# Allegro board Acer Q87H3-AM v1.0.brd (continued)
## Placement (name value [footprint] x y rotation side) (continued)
PFB8  -  [FB0603_1]  229.71 7.59 0 top
PFB9  -  [FB0805_1]  10.95 212.38 90 top
PFB10  -  [FB0603_1]  50.71 162.97 90 top
PFB11  -  [FB0603_1]  55.66 162.85 270 top
PFB12  -  [FB0805_1]  171.33 214.69 270 top
PFB13  -  [FB0805_1]  169.3 214.69 270 top
PSKM  -  [KB_MS]  234 235.23 270 top
Q1  -  [SOT363_6P]  10.7 237.01 0 top
Q2  -  [SOT363_6P]  18.32 237.01 0 top
Q3  -  [SOT363_6P]  20.86 237.01 0 top
Q4  -  [SOT363_6P]  15.78 237.01 0 top
Q5  -  [SOT363_6P]  6.76 231.05 180 top
Q6  -  [SOT363_6P]  13.24 237.01 0 top
Q7  -  [SOP8_W150_PT50]  103.03 204.63 0 top
QCH1  -  [Q_TDSON8-GDS-4]  161.96 187.74 0 top
QCH2  -  [Q_TDSON8-GDS-4]  179.86 187.74 0 top
QCH3  -  [Q_TDSON8-GDS-4]  213.65 178.34 0 top
QCH4  -  [Q_TDSON8-GDS-4]  142.02 187.74 0 top
QCL1  -  [Q_TDSON8-GDS-4]  156.5 171.1 270 top
QCL2  -  [Q_TDSON8-GDS-4]  177.07 171.1 270 top
QCL3  -  [Q_TDSON8-GDS-4]  222.79 167.29 90 top
QCL4  -  [Q_TDSON8-GDS-4]  137.45 171.1 270 top
QCL5  -  [Q_TDSON8-GDS-4]  156.5 180.5 270 top
QCL6  -  [Q_TDSON8-GDS-4]  177.07 180.5 270 top
QCL7  -  [Q_TDSON8-GDS-4]  222.79 175.42 90 top
QCL8  -  [Q_TDSON8-GDS-4]  137.45 180.5 270 top
QD3H1  -  [Q_TDSON8-GDS-4]  66.33 38.13 180 top
QD3L1  -  [Q_TDSON8-GDS-4]  71.41 53.5 90 top
QD3L2  -  [Q_TDSON8-GDS-4]  71.41 45.12 90 top
QD5H1  -  [Q_TDSON8-GDS-4]  63.28 21.24 0 top
QD5H2  -  [Q_TDSON8-GDS-4]  56.42 21.24 0 top
QD5L1  -  [Q_TDSON8-GDS-4]  49.56 9.18 270 top
QD5L2  -  [Q_TDSON8-GDS-4]  49.56 17.43 270 top
QMH1  -  [Q_TDSON8-GDS-4]  176.31 32.52 0 top
QML1  -  [Q_TDSON8-GDS-4]  170.29 30.26 180 top
QML2  -  [Q_TDSON8-GDS-4]  161.96 30.26 180 top
QN1  -  [SOT23_GDS_2]  203.49 145.83 0 top
QN2  -  [SOT23_BCE_2]  230.79 127.67 0 top
QN3  -  [SOT23_BCE_2]  234.47 127.67 0 top
QN4  -  [SOT23_BCE_2]  234.47 131.6 0 top
QN5  -  [SOT23_BCE_2]  230.79 131.6 0 top
QN6  -  [SOT23_GDS_2]  225.97 221.9 0 top
QN7  -  [SOT23_GDS_2]  218.22 217.33 90 top
QN8  -  [SOT23_GDS_2]  226.85 217.96 0 top
QN9  -  [SOT23_GDS_2]  222.03 217.2 0 top
QN10  -  [SOT23_GDS_2]  222.03 206.28 0 top
QN11  -  [SOT23_GDS_2]  217.08 206.28 0 top
QN12  -  [SOT23_GDS_2]  218.35 212.38 0 top
QN13  -  [SOT23_GDS_2]  222.03 212.38 0 top
QN20  -  [SOT23_GDS_2]  152.56 209.2 0 top
QN21  -  [SOT23_GDS_2]  148.24 209.2 0 top
QN22  -  [SOT23_GDS_2]  182.79 208.57 0 top
QN23  -  [SOT23_GDS_2]  156.5 209.2 0 top
QN24  -  [SOT23_BCE_2]  12.43 157.84 90 top
QN25  -  [SOT23_BCE_2]  12.43 161.53 90 top
QN26  -  [SOT23_BCE_2]  12.43 154.16 270 top
QN27  -  [SOT23_BCE_2]  13.13 165.21 270 top
QN28  -  [SOT23_BCE_2]  230.79 112.81 90 top
QN29  -  [SOT23_BCE_2]  226.98 112.68 0 top
QN30  -  [SOT23_GDS_2]  28.86 149.26 0 top
QN31  -  [SOT23_BCE_2]  28.86 145.32 0 top
QN32  -  [SOT23_BCE_2]  28.86 138.59 0 top
QN33  -  [SOT23_BCE_2]  32.67 138.59 180 top
QN34  -  [SOT23_GDS_2]  32.67 143.29 0 top
QN35  -  [SOT23_BCE_2]  20.73 87.15 90 top
QN36  -  [SOT23_GDS_2]  113.19 34.7 180 top
QN37  -  [SOT23_BCE_2]  123.48 34.7 180 top
QN38  -  [SOT23_GDS_2]  119.79 34.7 180 top
QN39  -  [SOT23_BCE_2]  127.16 34.7 0 top
QN40  -  [SOT23_BCE_2]  231.17 107.22 180 top
QN41  -  [SOT23_BCE_2]  13.24 58.2 90 top
QN42  -  [SOT23_BCE_2]  13.32 53.35 90 top
QN43  -  [SOT23_BCE_2]  10.34 49.66 90 top
QN44  -  [SOT23_GDS_2]  9.25 57.16 270 top
QN45  -  [SOT23_BCE_2]  205.01 203.49 0 top
QN46  -  [SOT23_BCE_2]  4.99 178.34 0 top
QN47  -  [SOT23_GDS_2]  109.89 5.11 90 top
QN48  -  [SOT23_BCE_2]  136.81 26.83 270 top
QN49  -  [SOT23_BCE_2]  129.19 26.07 180 top
QN50  -  [TO252_GDS]  145.96 9.43 0 top
QN51  -  [SOT23_BCE_2]  141.26 20.86 180 top
QN52  -  [TO252_GDS]  96.04 89.19 270 top
QN53  -  [SOT23_BCE_2]  103.16 99.47 180 top
QN54  -  [SOT23_BCE_2]  103.16 103.41 180 top
QN55  -  [SOT23_GDS_2]  96.93 109 180 top
QN56  -  [SOT23_GDS_2]  101 115.86 180 top
QN57  -  [SOT23_BCE_2]  97.31 120.05 180 top
QN58  -  [SOT23_GDS_2]  97.31 115.86 180 top
QN59  -  [SOT23_BCE_2]  101 120.05 180 top
QN60  -  [SOT23_BCE_2]  83.98 52.48 0 top
QN61  -  [SOT23_BCE_2]  119.79 30.77 0 top
QN62  -  [SOT23_BCE_2]  97.95 194.22 0 top
QN63  -  [SOT23_BCE_2]  91.98 192.18 270 top
QN64  -  [SOT23_BCE_2]  91.98 188.5 90 top
QN65  -  [SOT23_BCE_2]  4.81 150.48 180 top
QN66  -  [SOT23_BCE_2]  103.92 192.56 0 top
QN67  -  [SOT23_BCE_2]  99.09 188.37 90 top
QN68  -  [SOT23_GDS_2]  193.96 218.73 0 top
QN69  -  [SOT23_GDS_2]  188.88 213.54 90 top
QN71  -  [SOT23_GDS_2]  192.82 213.42 0 top
QN72  -  [SOT23_GDS_2]  184.56 204.25 270 top
QN73  -  [SOT23_GDS_2]  189.01 208.44 0 top
QN74  -  [SOT23_GDS_2]  190.53 204.25 0 top
QN75  -  [SOT23_GDS_2]  192.82 208.44 0 top
QN76  -  [SOT23_GDS_2]  167.8 204.5 0 top
QN77  -  [SOT23_BCE_2]  234.6 118.14 0 top
QN78  -  [SOT23_BCE_2]  234.6 122.08 0 top
QN79  -  [SOT23_BCE_2]  230.79 122.08 0 top
QN80  -  [SOT23_BCE_2]  230.79 118.14 0 top
QN81  -  [SOT23_BCE_2]  156.75 188.18 90 top
QN82  -  [SOT23_GDS_2]  229.71 4.99 0 top
QN83  -  [SOT23_BCE_2]  192.44 21.24 270 top
QN84  -  [SOT23_BCE_2]  190.15 17.56 90 top
QP2  -  [TO251_BCE_PT90_1]  120.05 193.33 0 top
QP3  -  [SOT23_BCE_2]  13.19 41.41 270 top
QP4  -  [SOT23_BCE_2]  28.35 213.27 0 top
QP5  -  [SOT23_BCE_2]  24.67 213.27 0 top
QP6  -  [SOT23_BCE_2]  32.04 213.27 0 top
QP7  -  [SOT23_BCE_2]  24.67 209.39 0 top
QP8  -  [SOT23_BCE_2]  83.85 65.69 90 top
QP9  -  [SOT23_GDS_2]  23.08 205.52 180 top
QSW1  -  [SOT23_GDS_2]  144.56 25.56 270 top
QSW2  -  [SOT23_GDS_2]  135.54 20.61 270 top
QSW3  -  [SOT23_GDS_2]  113.14 30.49 0 top
QSW4  -  [SOT23_GDS_2]  8.49 150.48 0 top
R1  -  [R0402_1]  134.91 135.8 270 top
R4  -  [R0402_1]  137.45 135.8 270 top
R5  -  [R0402_1]  205.9 147.61 270 top
R6  -  [R0402_1]  204.76 148.88 270 top
R7  -  [R0402_1]  198.66 148.75 0 top
R8  -  [R0402_1]  198.66 151.29 0 top
R9  -  [R0402_1]  202.85 151.29 180 top
R10  -  [R0402_1]  198.66 150.15 180 top
R11  -  [R0402_1]  202.85 148.75 0 top
R12  -  [R0402_1]  202.85 150.15 180 top
R13  -  [R0402_1]  123.1 137.57 0 top
R15  -  [R0402_1]  200.82 136.68 180 top
R16  -  [R0402_1]  200.82 125.89 180 top
R17  -  [R0402_1]  198.28 136.68 0 top
R18  -  [R0402_1]  198.28 128.56 180 top
R19  -  [R0402_1]  204.12 137.95 0 top
R20  -  [R0402_1]  198.28 129.95 180 top
R21  -  [R0402_1]  200.82 128.56 0 top
R22  -  [R0402_1]  200.82 129.95 0 top
R23  -  [R0402_1]  200.82 131.48 0 top
R24  -  [R0402_1]  210.73 123.86 270 top
R25  -  [R0402_1]  200.82 134.27 180 top
R26  -  [R0402_1]  134.91 137.95 270 top
R27  -  [R0402_1]  211.87 123.86 270 top
R28  -  [R0402_1]  200.82 132.87 0 top
R29  -  [R0402_1]  137.45 137.95 270 top
R30  -  [R0402_1]  198.28 131.48 180 top
R31  -  [R0402_1]  136.18 137.95 270 top
R32  -  [R0402_1]  198.28 135.54 180 top
R33  -  [R0402_1]  204.12 125.89 180 top
R34  -  [R0402_1]  204.12 127.03 180 top
R35  -  [R0402_1]  200.82 140.62 180 top
R36  -  [R0402_1]  198.28 132.87 180 top
R37  -  [R0402_1]  204.12 136.81 180 top
R38  -  [R0402_1]  198.28 140.62 180 top
R39  -  [R0402_1]  204.12 135.67 180 top
R40  -  [R0402_1]  204.25 142.15 180 top
R41  -  [R0402_1]  204.12 134.27 180 top
R42  -  [R0402_1]  200.82 143.03 180 top
R43  -  [R0402_1]  204.12 129.95 180 top
R44  -  [R0402_1]  204.12 128.56 180 top
R45  -  [R0402_1]  204.12 132.87 180 top
R46  -  [R0402_1]  211.08 119.44 90 top
R47  -  [R0402_1]  204.12 131.48 180 top
R48  -  [R0402_1]  211.36 121.57 90 top
R49  -  [R0402_1]  209.94 119.44 270 top
R50  -  [R0402_1]  204.12 124.75 180 top
R51  -  [R0402_1]  123.1 138.72 0 top
R52  -  [R0402_1]  198.28 134.27 180 top
R53  -  [R0402_1]  204.25 143.29 0 top
R56  -  [R0402_1]  198.28 144.43 0 top
R57  -  [R0402_1]  198.28 141.89 180 top
R58  -  [R0402_1]  200.82 141.76 180 top
R59  -  [R0402_1]  237.4 129.06 0 top
R60  -  [R0402_1]  237.34 127.26 180 top
R61  -  [R0402_1]  237.37 126.19 180 top
R62  -  [R0402_1]  237.4 132.49 0 top
R63  -  [R0402_1]  237.4 130.21 180 top
R64  -  [R0402_1]  229.39 134.14 180 top
R65  -  [R0402_1]  237.4 131.35 180 top
R66  -  [R0402_1]  207.17 119.54 90 top
R67  -  [R0402_1]  208.31 119.54 90 top
R68  -  [R0402_1]  173.01 77.63 180 top
R71  -  [R0402_1]  108.62 112.68 180 top
R72  -  [R0402_1]  200.82 137.95 180 top
R73  -  [R0402_1]  204.12 139.1 0 top
R75  -  [R0402_1]  224.44 218.09 90 top
R76  -  [R0402_1]  224.82 225.08 90 top
R77  -  [R0402_1]  217.58 220.25 90 top
R78  -  [R0402_1]  224.44 210.47 90 top
R79  -  [R0402_1]  223.68 228.25 90 top
R80  -  [R0805_1]  230.28 218.98 90 top
R81  -  [R0402_1]  216.82 208.74 0 top
R82  -  [R0402_1]  224.44 207.8 270 top
R83  -  [R0402_1]  224.44 215.68 270 top
R84  -  [R0805_1]  226.98 215.04 180 top
R85  -  [R0402_1]  217.84 209.84 0 top
R86  -  [R0402_1]  214.15 206.03 0 top
R87  -  [R0402_1]  217.46 214.92 180 top
R88  -  [R0402_1]  214.15 207.17 0 top
R89  -  [R0402_1]  224.44 213.52 90 top
R95  -  [R0402_1]  88.81 185.2 270 top
R96  -  [R0402_1]  87.66 185.2 270 top
R98  -  [R0402_1]  86.52 185.2 90 top
R103  -  [R0402_1]  149.51 212.25 270 top
R104  -  [R0402_1]  152.56 206.66 0 top
R105  -  [R0402_1]  150.65 212.25 270 top
R106  -  [R0402_1]  149 206.66 0 top
R107  -  [R0402_1]  156.24 206.66 0 top
R108  -  [R0402_1]  150.65 216.06 90 top
R109  -  [R0402_1]  146.97 212.12 90 top
R110  -  [R0402_1]  152.43 211.74 180 top
R111  -  [R0402_1]  155.23 211.74 180 top
R112  -  [R0402_1]  158.02 211.74 180 top
R113  -  [R0402_1]  145.7 58.71 90 top
R114  -  [R0402_1]  133.64 36.61 90 top
R115  -  [R0402_1]  147.99 58.71 270 top
R116  -  [R0402_1]  136.56 36.61 270 top
R117  -  [R0402_1]  146.84 58.71 270 top
R118  -  [R0402_1]  134.78 36.61 270 top
R119  -  [R0402_1]  215.25 59.11 270 top
R120  -  [R0402_1]  215.22 57 90 top
R121  -  [R0402_1]  218.68 59.11 90 top
R122  -  [R0402_1]  218.65 57 270 top
R123  -  [R0402_1]  216.36 59.11 90 top
R124  -  [R0402_1]  216.36 57 270 top
R125  -  [R0402_1]  226.73 58.33 90 top
R126  -  [R0402_1]  226.47 56.55 180 top
R127  -  [R0402_1]  36.74 74.71 90 top
R128  -  [R0805_1]  171.48 206.15 90 top
R129  -  [R0402_1]  63.28 97.7 180 top
R130  -  [R0402_1]  63.51 103.26 180 top
R131  -  [R0402_1]  69.5 97.06 90 top
R132  -  [R0402_1]  70.64 97.06 90 top
R133  -  [R0402_1]  61.37 66.71 0 top
R136  -  [R0402_1]  29.88 87.41 180 top
R137  -  [R0402_1]  29.88 88.68 180 top
R138  -  [R0402_1]  29.88 99.42 180 top
R139  -  [R0402_1]  49.69 72.8 90 top
R140  -  [R0402_1]  29.62 117.13 180 top
R141  -  [R0402_1]  29.62 115.98 180 top
R142  -  [R0402_1]  39.15 118.9 270 top
R143  -  [R0402_1]  38.01 118.9 270 top
R144  -  [R0402_1]  43.72 113.44 270 top
R145  -  [R0402_1]  42.58 113.44 270 top
R146  -  [R0402_1]  44.86 113.44 270 top
R147  -  [R0402_1]  40.42 113.44 270 top
R148  -  [R0402_1]  26.7 110.27 0 top
R149  -  [R0402_1]  63.53 105.57 0 top
R150  -  [R0402_1]  63.53 106.71 0 top
R151  -  [R0402_1]  27.21 108.62 0 top
R152  -  [R0402_1]  32.8 120.43 0 top
R153  -  [R0402_1]  53.75 112.88 180 top
R154  -  [R0402_1]  26.7 111.54 0 top
R155  -  [R0402_1]  27.08 106.71 0 top
R156  -  [R0402_1]  29.88 86.27 0 top
R157  -  [R0402_1]  141 36.61 270 top
R158  -  [R0402_1]  29.88 83.22 0 top
R159  -  [R0402_1]  29.5 109.25 0 top
R160  -  [R0402_1]  29.37 84.74 90 top
R161  -  [R0402_1]  30.51 84.74 270 top
R162  -  [R0603_1]  60.1 122.46 180 top
R163  -  [R0402_1]  63.28 79.28 0 top
R164  -  [R0402_1]  63.28 78.14 0 top
R165  -  [R0402_1]  66.45 78.9 0 top
R166  -  [R0402_1]  63.33 87.92 0 top
R167  -  [R0402_1]  61.37 67.85 0 top
R168  -  [R0402_1]  56.67 67.09 180 top
R169  -  [R0402_1]  57.69 68.74 270 top
R170  -  [R0402_1]  66.45 81.31 0 top
R171  -  [R0402_1]  54.9 66.58 270 top
R172  -  [R0402_1]  56.55 64.29 90 top
R173  -  [R0402_1]  64.68 76.36 90 top
R174  -  [R0402_1]  66.45 80.17 180 top
R175  -  [R0402_1]  53.75 66.96 270 top
R176  -  [R0402_1]  57.69 64.29 90 top
R177  -  [R0402_1]  25.31 89.19 90 top
R178  -  [R0402_1]  27.36 88.48 0 top
R179  -  [R0402_1]  66.2 77.76 180 top
R180  -  [R0402_1]  27.59 86.9 270 top
R181  -  [R0402_1]  8.87 161.27 270 top
R182  -  [R0402_1]  6.38 164.12 180 top
R183  -  [R0402_1]  8.41 163.48 270 top
R184  -  [R0402_1]  9.89 161.27 90 top
R185  -  [R0402_1]  9.43 156.5 180 top
R186  -  [R0402_1]  36.33 67.98 0 top
R187  -  [R0402_1]  9.43 153.45 270 top
R188  -  [R0402_1]  14.96 168.43 270 top
R189  -  [R0402_1]  12.99 169.01 0 top
R190  -  [R0402_1]  36.33 68.99 0 top
R191  -  [R0402_1]  36.33 70.26 0 top
R192  -  [R0402_1]  24.98 92.03 270 top
R193  -  [R0402_1]  63.28 82.96 0 top
R194  -  [R0402_1]  24.29 89.19 90 top
R195  -  [R0402_1]  42.88 69.25 90 top
R196  -  [R0402_1]  23.91 92.03 90 top
R197  -  [R0402_1]  50.32 70.64 90 top
R198  -  [R0402_1]  36.58 79.92 90 top
R199  -  [R0402_1]  30.03 94.27 180 top
R200  -  [R0402_1]  33.31 74.71 90 top
R201  -  [R0402_1]  52.61 66.96 270 top
R202  -  [R0402_1]  41.76 69.25 90 top
R203  -  [R0402_1]  41.94 75.93 270 top
R204  -  [R0402_1]  33.31 76.74 270 top
R205  -  [R0402_1]  39.02 67.98 0 top
R206  -  [R0402_1]  54.77 64.29 90 top
R207  -  [R0402_1]  26.5 98.32 0 top
R208  -  [R0402_1]  36.33 71.28 0 top
R209  -  [R0402_1]  53.75 64.29 90 top
R210  -  [R0402_1]  26.5 97.24 0 top
R211  -  [R0402_1]  50.71 72.78 270 top
R212  -  [R0402_1]  20.35 67.47 0 top
R213  -  [R0402_1]  48.17 66.83 180 top
R214  -  [R0402_1]  20.35 66.33 0 top
R215  -  [R0402_1]  43.14 71.36 270 top
R216  -  [R0402_1]  26.5 99.4 0 top
R217  -  [R0402_1]  27.11 96.12 0 top
R218  -  [R0402_1]  43.09 75.93 270 top
R219  -  [R0402_1]  48.17 69.12 180 top
R220  -  [R0402_1]  44.23 72.3 270 top
R221  -  [R0402_1]  49.56 76.49 90 top
R222  -  [R0402_1]  36.61 65.69 90 top
R223  -  [R0402_1]  33.69 63.02 90 top
R224  -  [R0402_1]  36.33 72.3 0 top
R225  -  [R0402_1]  24.16 77.88 180 top
R226  -  [R0402_1]  48.17 67.98 180 top
R227  -  [R0402_1]  22.38 67.47 180 top
R228  -  [R0402_1]  22.26 68.87 180 top
R229  -  [R0402_1]  34.45 74.71 90 top
R231  -  [R0402_1]  24.16 78.9 180 top
R232  -  [R0402_1]  39.28 71.91 180 top
R233  -  [R0402_1]  35.59 76.74 90 top
R234  -  [R0402_1]  22.13 82.84 270 top
R235  -  [R0402_1]  39.28 76.23 90 top
R236  -  [R0402_1]  48.42 75.98 270 top
R237  -  [R0402_1]  24.16 76.74 180 top
R238  -  [R0402_1]  24.16 75.72 180 top
R239  -  [R0402_1]  41.94 73.44 270 top
R240  -  [R0402_1]  43.14 73.44 90 top
R241  -  [R0402_1]  234.6 112.81 90 top
R242  -  [R0402_1]  231.17 115.6 0 top
R243  -  [R0402_1]  231.43 100.87 90 top
R244  -  [R0402_1]  10.19 70.9 0 top
R245  -  [R0402_1]  235.74 112.81 90 top
R246  -  [R0402_1]  233.46 112.81 90 top
R247  -  [R0402_1]  24.16 73.18 180 top
R248  -  [R0402_1]  24.16 74.2 180 top
R249  -  [R0603_1]  29.37 79.64 0 top
R250  -  [R0402_1]  230.41 46.77 0 top
R251  -  [R0402_1]  8.03 69.63 270 top
R252  -  [R0402_1]  34.58 76.74 270 top
R253  -  [R0402_1]  36.35 60.36 180 top
R254  -  [R0402_1]  7.14 66.45 0 top
R255  -  [R0402_1]  37.12 59.21 180 top
R256  -  [R0402_1]  36.35 61.37 0 top
R257  -  [R0603_1]  39.15 113.82 90 top
R258  -  [R0402_1]  199.3 15.27 180 top
R259  -  [R0402_1]  32.16 79.92 90 top
R260  -  [R0603_1]  32.29 149.51 180 top
R261  -  [R0402_1]  31.91 151.16 0 top
R262  -  [R0402_1]  27.72 141.64 90 top
R263  -  [R0402_1]  28.86 141.64 90 top
R264  -  [R0402_1]  28.48 135.41 0 top
R265  -  [R0402_1]  30.77 135.41 0 top
R266  -  [R0805_1]  32.54 146.21 180 top
R267  -  [R0402_1]  32.04 148.24 180 top
R268  -  [R0402_1]  33.69 135.41 0 top
R269  -  [R0402_1]  30 141.64 90 top
R270  -  [R0402_1]  26.32 186.09 0 top
R271  -  [R0402_1]  67.34 184.44 270 top
R275  -  [R0402_1]  60.23 136.56 90 top
R276  -  [R0603-SHORT_1]  73.31 150.91 180 top
R277  -  [R0402_1]  69.12 138.21 0 top
R278  -  [R0402_1]  69.12 137.07 0 top
R279  -  [R0402_1]  69.76 149.64 270 top
R280  -  [R0402_1]  74.07 143.67 90 top
R281  -  [R0402_1]  75.22 143.67 90 top
R282  -  [R0402_1]  52.1 137.45 270 top
R283  -  [R0402_1]  54.39 137.45 270 top
R284  -  [R0402_1]  47.78 145.07 180 top
R285  -  [R0402_1]  47.78 142.78 180 top
R286  -  [R0402_1]  47.78 143.92 180 top
R287  -  [R0402_1]  53.25 137.45 270 top
R288  -  [R0402_1]  47.91 151.16 180 top
R289  -  [R0402_1]  33.69 180.88 90 top
R290  -  [R0402_1]  48.29 180.75 0 top
R291  -  [R0402_1]  47.53 162.59 180 top
R292  -  [R0402_1]  47.28 132.11 180 top
R293  -  [R0402_1]  47.28 130.97 180 top
R294  -  [R0402_1]  10.57 109.13 0 top
R295  -  [R0402_1]  14.26 128.05 180 top
R296  -  [R0402_1]  4.48 122.33 180 top
R297  -  [R0402_1]  7.65 98.2 0 top
R298  -  [R0402_1]  139.73 217.58 0 top
R299  -  [R0402_1]  142.78 227.36 0 top
R300  -  [R0402_1]  13.49 38.51 90 top
R301  -  [R0402_1]  110.27 34.2 0 top
R302  -  [R0402_1]  117.38 33.81 270 top
R303  -  [R0402_1]  110.27 35.34 0 top
R304  -  [R0402_1]  110.27 36.48 180 top
R305  -  [R0402_1]  116.24 35.97 270 top
R306  -  [R0402_1]  125.64 30.64 270 top
R307  -  [R0402_1]  126.78 30.64 270 top
R308  -  [R0402_1]  117.38 35.97 270 top
R309  -  [R0402_1]  129.57 35.59 90 top
R310  -  [R0402_1]  21.5 9.7 90 top
R311  -  [R0402_1]  25.81 9.68 90 top
R312  -  [R0402_1]  35.59 9.58 90 top
R313  -  [R0402_1]  42.45 10.07 90 top
R314  -  [R0402_1]  37.88 10.07 270 top
R316  -  [R0402_1]  40.16 10.07 90 top
R317  -  [R0402_1]  32.04 9.56 270 top
R318  -  [R0402_1]  33.18 9.56 270 top
R319  -  [R0402_1]  30.89 9.56 90 top
R320  -  [R0402_1]  39.02 10.07 90 top
R321  -  [R0402_1]  29.75 9.56 90 top
R322  -  [R0402_1]  41.31 10.07 270 top
R323  -  [R0402_1]  22.64 9.7 90 top
R324  -  [R0402_1]  34.45 9.58 90 top
R325  -  [R0402_1]  24.16 9.68 270 top
R326  -  [R0402_1]  24.04 13.11 270 top
R329  -  [R0402_1]  218.35 10.95 0 top
R330  -  [R0402_1]  214.41 8.92 0 top
R331  -  [R0402_1]  227.05 10.57 90 top
R332  -  [R0402_1]  225.9 10.57 90 top
R333  -  [R0402_1]  220.63 8.92 0 top
R334  -  [R0402_1]  218.54 8.92 0 top
R335  -  [R0402_1]  220.06 11.84 270 top
R336  -  [R0402_1]  220.89 10.19 0 top
R337  -  [R0402_1]  223.68 10.45 90 top
R338  -  [R0402_1]  222.54 10 90 top
R339  -  [R0402_1]  216 10.13 180 top
R340  -  [R0402_1]  217.84 12.92 270 top
R341  -  [R0402_1]  224.31 34.91 0 top
R342  -  [R0402_1]  207.36 10.32 270 top
R343  -  [R0402_1]  210.73 36.48 0 top
R344  -  [R0402_1]  208.25 13.11 270 top
R345  -  [R0402_1]  197.26 25.81 270 top
R347  -  [R0603-SHORT_1]  232.44 38.39 180 top
R349  -  [R0402_1]  209.07 35.85 270 top
R350  -  [R0402_1]  205.58 13.24 270 top
R351  -  [R0402_1]  213.21 36.48 0 top
R352  -  [R0402_1]  216.95 35.85 90 top
R353  -  [R0402_1]  215.3 36.48 0 top
R354  -  [R0402_1]  224.11 36.48 90 top
R355  -  [R0402_1]  206.73 13.24 270 top
R356  -  [R0402_1]  209.39 13.11 270 top
R357  -  [R0402_1]  196.93 22.92 180 top
R358  -  [R0402_1]  198.66 28.23 0 top
R359  -  [R0402_1]  14.26 126.91 180 top
R360  -  [R0402_1]  195.36 20.1 90 top
R365  -  [R0603-SHORT_1]  233.33 43.59 90 top
R366  -  [FB0603_1]  210.66 10.62 270 top
R367  -  [R0402_1]  240.32 39.28 270 top
R368  -  [R0402_1]  232.06 44.1 270 top
R369  -  [R0402_1]  233.33 93.25 90 top
R370  -  [R0402_1]  115.6 183.42 90 top
R371  -  [R0402_1]  121.19 191.29 180 top
R372  -  [R0402_1]  233.33 95.28 90 top
R373  -  [R0402_1]  112.94 186.72 90 top
R374  -  [R0402_1]  119.03 191.29 180 top
R375  -  [R0805_1]  121.95 196.63 0 top
R376  -  [R0402_1]  233.33 91.22 90 top
R377  -  [R0402_1]  233.33 97.44 270 top
R378  -  [R0402_1]  233.33 89.06 90 top
R379  -  [R0402_1]  120.43 183.42 270 top
R380  -  [R0402_1]  114.08 186.72 270 top
R381  -  [R0402_1]  115.6 186.72 270 top
R382  -  [R0402_1]  119.29 183.42 90 top
R383  -  [R0402_1]  118.14 183.42 90 top
R384  -  [R0402_1]  116.75 183.42 270 top
R385  -  [R0402_1]  232.95 99.22 0 top
R386  -  [R0402_1]  10.59 171.05 270 top
R387  -  [R0402_1]  232.57 100.87 90 top
R388  -  [R0402_1]  14.26 55.79 0 top
R389  -  [R0402_1]  12.86 48.17 270 top
R390  -  [R0402_1]  11.34 47.33 0 top
R391  -  [R0603_1]  3.84 57.31 270 top
R392  -  [R0603_1]  9.81 40.42 0 top
R393  -  [R0603_1]  9.76 54.49 0 top
R394  -  [R0603_1]  9.76 52.97 0 top
R395  -  [R0402_1]  14.84 50.55 270 top
R396  -  [R0402_1]  12.22 55.79 180 top
R397  -  [R0402_1]  14 48.17 270 top
R398  -  [R0402_1]  13.7 50.55 90 top
R400  -  [R0402_1]  6.2 58.17 180 top
R401  -  [R0603_1]  5.95 56.9 0 top
R402  -  [R0402_1]  181.77 10.32 90 top
R403  -  [R0402_1]  224.95 4.71 180 top
R404  -  [R0603_1]  232.32 16.48 270 top
R405  -  [R0402_1]  224.95 5.8 0 top
R406  -  [R0603_1]  234.86 16.16 270 top
R407  -  [R0603_1]  234.6 28.04 270 top
R408  -  [R0402_1]  237.01 27.34 270 top
R409  -  [R0402_1]  194.29 6.05 270 top
R410  -  [R0402_1]  222.54 7.91 180 top
R411  -  [R0402_1]  222.54 6.89 180 top
R412  -  [R0402_1]  238.09 27.34 90 top
R413  -  [R0402_1]  222.54 3.59 0 top
R414  -  [R0402_1]  202.6 204.63 270 top
R415  -  [R0402_1]  18.57 10.45 0 top
R416  -  [R0402_1]  222.54 5.8 0 top
R417  -  [R0402_1]  225.14 8.99 180 top
R418  -  [R0402_1]  202.6 202.47 90 top
R419  -  [R0402_1]  18.57 9.18 180 top
R420  -  [R0402_1]  222.54 4.71 0 top
R421  -  [R0402_1]  216.44 8.92 0 top
R422  -  [R0402_1]  19.08 6.76 90 top
R423  -  [R0402_1]  39.28 73.06 180 top
R424  -  [R0402_1]  199.3 16.42 180 top
R425  -  [R0402_1]  60.23 221.39 0 top
R426  -  [R0402_1]  60.48 206.41 270 top
R427  -  [R0402_1]  65.95 221.01 270 top
R428  -  [R0402_1]  60.23 220.25 0 top
R429  -  [R0402_1]  9.56 39.02 180 top
R430  -  [R0402_1]  74.96 221.27 270 top
R431  -  [R0402_1]  68.23 209.2 180 top
R432  -  [R0402_1]  70.14 221.27 270 top
R433  -  [R0402_1]  60.23 219.11 0 top
R434  -  [R0402_1]  68.61 207.55 270 top
R435  -  [R0402_1]  62.77 206.41 90 top
R436  -  [R0402_1]  61.63 206.41 270 top
R437  -  [R0402_1]  63.91 206.41 90 top
R438  -  [R0402_1]  65.06 206.41 90 top
R440  -  [R0402_1]  60.23 218.04 0 top
R441  -  [R0805_1]  82.07 207.8 90 top
R442  -  [R0402_1]  77.12 223.43 180 top
R443  -  [R0402_1]  77.12 225.46 180 top
R444  -  [R0402_1]  66.45 207.68 90 top
R445  -  [R0402_1]  71.15 221.27 270 top
R446  -  [R0402_1]  75.85 208.82 90 top
R447  -  [R0402_1]  69.12 221.27 90 top
R448  -  [R0402_1]  68.1 221.27 90 top
R449  -  [R0402_1]  53.5 221.27 90 top
R450  -  [R0805_1]  18.07 202.66 180 top
R451  -  [R0402_1]  56.8 222.92 270 top
R452  -  [R0402_1]  56.67 237.27 90 top
R453  -  [R0402_1]  43.09 221.27 270 top
R454  -  [R0402_1]  53.63 237.27 270 top
R455  -  [R0805-SHORT-NMNP]  69.44 227.05 90 top
R456  -  [R0402_1]  39.02 69.12 180 top
R457  -  [R0402_1]  64.8 221.01 90 top
R458  -  [R0402_1]  43.34 234.73 180 top
R459  -  [R0402_1]  43.34 235.87 180 top
R460  -  [R0402_1]  43.72 233.59 0 top
R461  -  [R0402_1]  58.71 237.27 90 top
R462  -  [R0603_1]  80.04 221.01 0 top
R463  -  [R0603_1]  80.04 218.22 0 top
R464  -  [R0603_1]  77.12 218.22 180 top
R465  -  [R0603_1]  77.12 221.01 180 top
R466  -  [R0603_1]  77.12 219.62 180 top
R467  -  [R0603_1]  119.54 215.04 270 top
R468  -  [R0402_1]  125.89 218.85 0 top
R469  -  [R0603-SHORT_1]  117.89 211.23 270 top
R470  -  [R0603-SHORT_1]  107.86 212.12 180 top
R471  -  [R0402_1]  27.08 208.69 90 top
R472  -  [R0402_1]  15.4 233.33 90 top
R473  -  [R0402_1]  13.11 233.71 90 top
R474  -  [R0402_1]  31.4 210.73 180 top
R475  -  [R0402_1]  11.34 231.05 180 top
R476  -  [R0402_1]  31.43 209.51 180 top
R477  -  [R0402_1]  19.59 233.71 90 top
R479  -  [R0402_1]  22.26 210.98 270 top
R480  -  [R0402_1]  11.97 216.44 90 top
R481  -  [R0402_1]  11.84 229.27 270 top
R482  -  [R0402_1]  10.7 229.27 270 top
R483  -  [R0402_1]  11.27 239.94 270 top
R484  -  [R0402_1]  9.56 233.71 270 top
R485  -  [R0402_1]  10.7 233.71 270 top
R486  -  [R0402_1]  10.19 239.94 270 top
R487  -  [R0402_1]  19.21 239.94 270 top
R488  -  [R0402_1]  18.57 233.71 90 top
R489  -  [R0402_1]  17.56 233.71 90 top
R490  -  [R0402_1]  23.15 235.62 180 top
R491  -  [R0402_1]  11.72 221.65 0 top
R492  -  [R0402_1]  25.18 235.62 0 top
R493  -  [R0402_1]  18.13 239.94 270 top
R494  -  [R0402_1]  23.15 240.32 180 top
R495  -  [R0402_1]  25.31 240.32 180 top
R496  -  [R0402_1]  21.5 239.94 270 top
R497  -  [R0402_1]  32.42 224.7 90 top
R498  -  [R0402_1]  33.56 224.7 90 top
R499  -  [R0402_1]  25.43 217.33 0 top
R500  -  [R0402_1]  29.75 217.33 0 top
R501  -  [R0402_1]  20.35 239.94 270 top
R502  -  [R0402_1]  27.59 217.33 0 top
R503  -  [R0402_1]  16.35 239.94 270 top
R504  -  [R0402_1]  22.26 214.03 270 top
R505  -  [R0402_1]  15.4 208.95 90 top
R507  -  [R0402_1]  15.27 239.94 270 top
R508  -  [R0603-SHORT_1-NMNP]  3.84 174.78 270 top
R509  -  [R0402_1]  17.43 208.95 270 top
R510  -  [R0402_1]  17.43 211.11 270 top
R511  -  [R0402_1]  6.51 233.84 270 top
R512  -  [R0603-SHORT_1-NMNP]  83.22 220.89 270 top
R513  -  [R0402_1]  7.65 233.84 270 top
R514  -  [R0402_1]  11.97 233.71 270 top
R515  -  [R0402_1]  14.07 239.94 270 top
R516  -  [R0805_1]  8.29 178.59 270 top
R517  -  [R0402_1]  4.99 181.39 90 top
R518  -  [R0402_1]  3.72 181.39 90 top
R519  -  [R0402_1]  14.26 233.71 270 top
R520  -  [R0402_1]  12.99 239.94 270 top
R523  -  [R0402_1]  3.72 232.57 90 top
R524  -  [R0402_1]  3.72 229.78 90 top
R525  -  [R0402_1]  4.73 213.52 90 top
R526  -  [R0402_1]  8.16 213.52 90 top
R528  -  [R0402_1]  70.01 236.51 0 top
R529  -  [R0402_1]  81.69 224.19 270 top
R530  -  [R0402_1]  86.52 239.94 270 top
R531  -  [R0402_1]  70.14 239.05 0 top
R551  -  [R0402_1]  46.64 68.1 90 top
R552  -  [R0402_1]  45.65 64.45 180 top
R554  -  [R0402_1]  44.99 69.25 90 top
R555  -  [R0402_1]  46.64 70.14 270 top
R558  -  [R0402_1]  45.24 75.22 90 top
R561  -  [R0402_1]  43.97 66.83 90 top
R562  -  [R0402_1]  44.99 66.83 270 top
R563  -  [R0603_1]  155.61 19.08 270 top
R564  -  [R0805_1]  162.21 21.5 180 top
R565  -  [R0805_1]  162.21 23.4 180 top
R566  -  [R0402_1]  102.27 29.62 180 top
R567  -  [R0805_1]  174.15 17.81 180 top
R568  -  [R0402_1]  100.49 30.13 90 top
R569  -  [R0805_1]  180.37 26.58 270 top
R570  -  [R0402_1]  166.4 18.83 270 top
R571  -  [R0402_1]  177.58 28.2 0 top
R572  -  [R0805_1]  167.42 35.08 180 top
R573  -  [R0805_1]  166.12 30.13 270 top
R574  -  [R0402_1]  175.29 23.02 270 top
R575  -  [R2512_1]  109.89 11.21 270 top
R576  -  [R0402_1]  155.86 23.02 90 top
R577  -  [R0402_1]  161.45 19.84 180 top
R578  -  [R0402_1]  165.64 22.18 180 top
R579  -  [R0402_1]  161.45 18.7 180 top
R580  -  [R0402_1]  141.76 26.32 90 top
R582  -  [R0402_1]  129.32 31.15 270 top
R583  -  [R0402_1]  126.78 25.05 270 top
R584  -  [R0402_1]  137.32 23.15 180 top
R585  -  [R0402_1]  133.38 25.31 90 top
R586  -  [R0402_1]  126.78 27.08 90 top
R588  -  [R0402_1]  128.68 28.61 0 top
R589  -  [R0402_1]  140.11 5.37 90 top
R590  -  [R0402_1]  132.24 25.31 270 top
R591  -  [R0402_1]  100.62 95.54 270 top
R592  -  [R0603_1]  90.71 94.27 90 top
R593  -  [R0402_1]  106.2 100.11 0 top
R595  -  [R0402_1]  106.2 103.54 0 top
R596  -  [R0402_1]  101.76 95.54 90 top
R597  -  [R0805_1]  80.3 69.25 270 top
R598  -  [R0402_1]  106.2 104.68 0 top
R599  -  [R0805_1]  78.26 69.25 270 top
R600  -  [R0402_1]  106.2 102.39 180 top
R601  -  [R0402_1]  96.04 93.89 270 top
R602  -  [R0402_1]  103.54 112.17 90 top
R603  -  [R0603_1]  90.71 97.19 90 top
R604  -  [R0402_1]  102.39 112.17 90 top
R606  -  [R0402_1]  105.82 119.16 270 top
R607  -  [R0402_1]  104.55 119.16 90 top
R608  -  [R0402_1]  101.25 112.17 270 top
R609  -  [R0402_1]  98.71 122.71 0 top
R610  -  [R0805_1]  97.14 112.91 180 top
R611  -  [R0402_1]  102.14 109.13 0 top
R612  -  [R0402_1]  104.81 121.19 0 top
R613  -  [R0402_1]  103.41 119.16 90 top
R614  -  [R0402_1]  82.71 49.18 90 top
R615  -  [R0402_1]  85.71 57.08 0 top
R616  -  [R0402_1]  84.49 60.99 180 top
R617  -  [R0402_1]  85.25 58.71 270 top
R618  -  [R0402_1]  85 62.14 180 top
R619  -  [R0402_1]  81.19 66.2 270 top
R620  -  [R0402_1]  82.33 60.99 0 top
R621  -  [R0402_1]  84.11 49.18 90 top
R622  -  [R0402_1]  85.25 49.18 90 top
R623  -  [SHORT2-NMNP]  124.37 28.61 270 top
R624  -  [R0402_1]  112.3 19.21 270 top
R625  -  [R0402_1]  122.21 30.64 270 top
R626  -  [R0402_1]  112.15 17.08 90 top
R627  -  [R0402_1]  116.24 29.88 270 top
R628  -  [R0402_1]  123.35 30.64 90 top
R629  -  [R0402_1]  104.68 112.17 270 top
R630  -  [R0402_1]  116.24 32.04 90 top
R631  -  [SHORT2-NMNP]  122.84 28.61 270 top
R632  -  [R0603_1]  97.06 198.28 90 top
R633  -  [R0402_1]  95.03 190.02 0 top
R634  -  [R0805_1]  103.28 196.25 270 top
R635  -  [R0805_1]  101.25 196.25 270 top
R636  -  [R0402_1]  98.33 198.15 270 top
R637  -  [R0402_1]  95.03 191.17 0 top
R638  -  [R0402_1]  95.03 193.45 180 top
R639  -  [R0805_1]  96.68 201.96 270 top
R640  -  [R0805_1]  94.65 201.96 270 top
R641  -  [R0402_1]  95 185.3 0 top
R642  -  [R0402_1]  10.9 148.32 90 top
R643  -  [R0402_1]  6.69 147.96 180 top
R644  -  [R0402_1]  95.03 187.48 0 top
R645  -  [R0402_1]  8.29 153.45 270 top
R646  -  [R0402_1]  12.53 150.73 180 top
R647  -  [R0402_1]  102.65 187.23 180 top
R648  -  [R0402_1]  102.65 188.37 180 top
R649  -  [R0402_1]  104.93 196.37 270 top
R650  -  [R0402_1]  95.03 192.31 180 top
R651  -  [R0402_1]  10.9 150.86 90 top
R652  -  [R0402_1]  104.81 190.02 0 top
R653  -  [R0402_1]  100.16 183.4 270 top
R654  -  [R0402_1]  102.65 190.02 0 top
R657  -  [R0402_1]  99.07 183.4 270 top
R694  -  [R0402_1]  57.69 237.27 270 top
R695  -  [R0402_1]  77.12 222.28 0 top
R737  -  [R0402_1]  62.92 209.33 0 top
R738  -  [R0402_1]  42.2 59.98 270 top
R739  -  [R0402_1]  200.82 127.03 0 top
R740  -  [R0402_1]  27.36 89.57 0 top
R741  -  [R0402_1]  207.93 35.59 90 top
R760  -  [R0603_1]  47.53 120.3 270 top
R761  -  [R0402_1]  24.42 70.01 180 top
R762  -  [R0402_1]  62.9 236.51 90 top
R763  -  [R0402_1]  59.72 237.27 90 top
R764  -  [R0402_1]  36.74 10.07 90 top
R765  -  [R0402_1]  28.61 9.56 90 top
R766  -  [R0402_1]  85.25 213.9 270 top
R767  -  [R0402_1]  84.23 213.9 270 top
R768  -  [R0402_1]  82.71 213.9 270 top
R769  -  [R0402_1]  81.69 213.9 270 top
R770  -  [R0402_1]  77.12 214.92 180 top
R771  -  [R0402_1]  77.12 215.93 180 top
R772  -  [R0402_1]  86.27 213.9 90 top
R773  -  [R0402_1]  87.28 213.9 90 top
R777  -  [R0402_1]  93.38 93.63 180 top
R778  -  [R0402_1]  99.35 107.47 90 top
R783  -  [R0402_1]  193.96 216.19 180 top
R784  -  [R0402_1]  195.23 221.77 90 top
R786  -  [R0402_1]  187.99 215.93 0 top
R787  -  [R0402_1]  194.09 221.77 90 top
R789  -  [R0402_1]  187.61 205.39 0 top
R790  -  [R0402_1]  186.34 207.8 90 top
R791  -  [R0402_1]  194.29 210.93 180 top
R793  -  [R0402_1]  188.12 203.49 270 top
R794  -  [R0402_1]  188.25 210.98 180 top
R795  -  [R0402_1]  181.01 205.14 270 top
R796  -  [R0402_1]  182.15 205.14 270 top
R797  -  [R0402_1]  195.23 208.44 90 top
R798  -  [R0402_1]  167.04 201.96 0 top
R799  -  [R0402_1]  163.74 213.77 0 top
R800  -  [R0402_1]  161.45 213.77 0 top
R801  -  [R0402_1]  165.39 215.04 270 top
R802  -  [R0402_1]  166.53 215.04 270 top
R803  -  [R0402_1]  159.67 201.96 180 top
R804  -  [R0402_1]  163.35 207.04 180 top
R805  -  [R0402_1]  159.67 207.04 0 top
R808  -  [R0402_1]  123.35 3.84 0 top
R809  -  [R0603_1]  128.81 15.86 0 top
R810  -  [R0402_1]  220.5 142.78 0 top
R811  -  [R0603_1]  237.27 151.67 180 top
R812  -  [R0603_1]  221.9 157.77 270 top
R813  -  [R0805_1]  167.55 181.19 0 top
R814  -  [R0402_1]  218.85 145.83 90 top
R815  -  [R0402_1]  220.5 143.92 180 top
R816  -  [R0402_1]  216.57 145.83 90 top
R817  -  [R0603_1]  229.9 160.69 270 top
R818  -  [R0402_1]  217.71 145.83 90 top
R819  -  [R0402_1]  223.81 142.4 90 top
R820  -  [R0402_1]  220.5 141.64 0 top
R821  -  [R0402_1]  164.75 181.01 180 top
R822  -  [R0805_1]  150.65 182.4 90 top
R823  -  [R0402_1]  210.73 159.93 270 top
R824  -  [R0402_1]  223.81 144.94 90 top
R825  -  [R0603_1]  237.52 157.77 270 top
R826  -  [R0402_1]  211.87 155.23 90 top
R827  -  [R0402_1]  210.73 155.23 90 top
R828  -  [R0402_1]  220.5 150.15 0 top
R829  -  [R0805_1]  155.61 175.8 180 top
R830  -  [R0402_1]  209.58 159.93 270 top
R831  -  [R0402_1]  220.5 149 0 top
R832  -  [R0402_1]  210.73 157.39 90 top
R833  -  [R0402_1]  209.58 155.23 90 top
R834  -  [R0603_1]  233.46 157.77 270 top
R835  -  [R0402_1]  211.87 159.93 270 top
R836  -  [R0805_1]  185.07 182.66 0 top
R837  -  [R0402_1]  226.55 141.97 180 top
R838  -  [R0402_1]  182.66 182.66 270 top
R839  -  [R0402_1]  228.89 140.88 180 top
R840  -  [R0402_1]  228.96 143.21 180 top
R841  -  [R0603_1]  223.7 157.77 270 top
R842  -  [R0805_1]  175.8 175.8 180 top
R843  -  [R0402_1]  228.96 141.97 180 top
R844  -  [R0805_1]  171.74 177.71 270 top
R845  -  [R0402_1]  214.15 159.93 270 top
R846  -  [R0402_1]  235.62 140.37 180 top
R847  -  [R0402_1]  228.89 144.3 180 top
R848  -  [R0402_1]  213.01 159.93 270 top
R849  -  [R0402_1]  231.05 142.02 180 top
R850  -  [R0402_1]  230.97 144.3 180 top
R851  -  [R0402_1]  233.97 141.38 90 top
R852  -  [R0402_1]  215.3 155.23 90 top
R853  -  [R0402_1]  214.15 155.23 90 top
R854  -  [R0402_1]  232.82 141.38 90 top
R855  -  [R0402_1]  214.15 157.39 90 top
R856  -  [R0402_1]  233.78 144.3 0 top
R857  -  [R0402_1]  213.01 155.23 90 top
R858  -  [R0402_1]  230.97 145.45 0 top
R859  -  [R0402_1]  215.3 159.93 270 top
R860  -  [R0805_1]  217.91 178.98 90 top
R861  -  [R0402_1]  222.16 140.24 0 top
R862  -  [R0402_1]  223.55 150.78 0 top
R863  -  [R0402_1]  220.5 151.29 0 top
R864  -  [R0402_1]  223.55 151.92 180 top
R865  -  [R0402_1]  224.95 144.94 270 top
R866  -  [R0402_1]  217.96 175.93 270 top
R867  -  [R0402_1]  237.9 144.41 90 top
R868  -  [R0402_1]  236.76 144.43 90 top
R869  -  [R0805_1]  224.57 171.36 0 top
R870  -  [R0805_1]  227.62 177.71 90 top
R871  -  [R0402_1]  224.95 142.4 270 top
R872  -  [R0402_1]  233.97 147.1 90 top
R873  -  [R0402_1]  218.73 159.93 270 top
R874  -  [R0402_1]  232.82 147.1 90 top
R875  -  [R0402_1]  235.24 147.1 90 top
R876  -  [R0402_1]  217.58 159.93 270 top
R877  -  [R0402_1]  218.73 155.23 90 top
R878  -  [R0402_1]  217.58 155.23 90 top
R879  -  [R0402_1]  217.58 157.39 90 top
R880  -  [R0402_1]  216.44 155.23 90 top
R881  -  [R0402_1]  216.44 159.93 270 top
R882  -  [R0603_1]  147.73 181.26 0 top
R883  -  [R0805_1]  151.35 186.85 270 top
R884  -  [R0805_1]  147.23 186.72 0 top
R885  -  [R0402_1]  144.43 183.29 0 top
R886  -  [R0402_1]  234.35 124.62 0 top
R887  -  [R0402_1]  233.33 115.6 180 top
R888  -  [R0805_1]  136.43 175.8 180 top
R889  -  [R0402_1]  227.11 125 0 top
R890  -  [R0402_1]  232.19 124.62 0 top
R891  -  [R0402_1]  227.11 120.43 180 top
R892  -  [R0402_1]  235.49 115.6 0 top
R893  -  [R0805_1]  134.4 185.33 90 top
R894  -  [R0402_1]  227.11 121.57 0 top
R895  -  [R0402_1]  229.01 115.6 0 top
R896  -  [R0402_1]  227.11 123.86 180 top
R897  -  [R0402_1]  227.11 119.29 0 top
R898  -  [R0402_1]  207.3 159.93 270 top
R899  -  [R0402_1]  206.15 159.93 270 top
R900  -  [R0402_1]  208.44 155.23 90 top
R901  -  [R0402_1]  206.15 155.23 90 top
R902  -  [R0402_1]  207.3 157.39 90 top
R903  -  [R0402_1]  207.3 155.23 90 top
R904  -  [R0402_1]  208.44 159.93 270 top
R905  -  [R0402_1]  45.5 34.32 180 top
R906  -  [R0402_1]  48.29 34.32 0 top
R907  -  [R0603_1]  50.58 28.35 270 top
R908  -  [R0805_1]  45.5 38.39 90 top
R909  -  [R0402_1]  47.02 39.02 270 top
R910  -  [R0805_1]  44.86 21.5 0 top
R911  -  [R0402_1]  60.23 31.66 90 top
R912  -  [R0402_1]  47.53 37.37 180 top
R913  -  [R0805_1]  48.11 13.32 180 top
R914  -  [R0402_1]  54.9 27.97 0 top
R915  -  [R0402_1]  54.9 26.83 180 top
R916  -  [R0402_1]  46.13 26.32 0 top
R917  -  [R0402_1]  59.98 29.12 90 top
R918  -  [R0402_1]  58.2 30.77 180 top
R919  -  [R0402_1]  58.33 29.62 0 top
R920  -  [R0603_1]  51.29 40.29 90 top
R921  -  [R0402_1]  56.55 29.24 270 top
R922  -  [R0805_1]  60.31 40.37 180 top
R923  -  [R0402_1]  62.59 41.21 90 top
R924  -  [R0402_1]  59.9 33.69 270 top
R925  -  [R0805_1]  78.39 41.82 270 top
R926  -  [R0805_1]  72.42 49.44 0 top
R927  -  [R0402_1]  60.87 37.5 0 top
R928  -  [R0402_1]  60.87 38.77 0 top
R929  -  [R0402_1]  58.71 36.35 180 top
R930  -  [R0402_1]  55.79 40.47 90 top
R931  -  [R0402_1]  56.93 40.47 270 top
R932  -  [R0402_1]  58.71 37.62 0 top
R933  -  [R0402_1]  60.87 36.35 0 top
R934  -  [R0402_1]  45.5 33.05 180 top
R935  -  [R0402_1]  48.29 33.05 0 top
R936  -  [R0402_1]  54.9 38.51 90 top
R937  -  [SHORT2-NMNP]  213.52 11.46 0 top
R938  -  [R0402_1]  7.53 139.61 270 top
R939  -  [R0402_1]  234.79 149.19 270 top
R941  -  [SHORT2-NMNP]  227.93 28.48 0 top
R942  -  [R0402_1]  203.68 13.43 0 top
R943  -  [R0402_1]  203.68 12.35 180 top
R944  -  [R0402_1]  194.16 16.29 270 top
R945  -  [R0402_1]  194.16 14.13 270 top
R949  -  [R0402_1]  43.72 227.87 0 top
R950  -  [R0402_1]  43.34 229.01 180 top
R951  -  [R0402_1]  43.34 230.16 180 top
R952  -  [R0402_1]  41.69 231.05 90 top
R953  -  [R0402_1]  53.17 239.25 0 top
R954  -  [R0402_1]  163.74 216.69 0 top
R955  -  [R0402_1]  161.58 216.69 0 top
R956  -  [R0402_1]  227.36 7.46 270 top
R957  -  [R0402_1]  64.04 236.51 90 top
R958  -  [R0402_1]  61.5 238.67 90 top
R959  -  [R0402_1]  215.3 35.34 180 top
R960  -  [R0402_1]  96.68 95.54 0 top
R961  -  [R0402_1]  100.49 107.47 270 top
R962  -  [R0402_1]  121.83 19.97 270 top
R963  -  [R0402_1]  47 65.67 180 top
R964  -  [R0402_1]  98.2 202.22 270 top
R965  -  [R0402_1]  47.91 152.31 180 top
R966  -  [R0402_1]  47.91 153.45 180 top
R967  -  [R0402_1]  47.91 157.13 180 top
R968  -  [R0402_1]  47.91 155.99 180 top
R969  -  [R0402_1]  47.91 154.59 180 top
R970  -  [R0402_1]  59.21 137.45 270 top
R971  -  [R0402_1]  49.69 159.93 90 top
R972  -  [R0402_1]  50.83 159.93 90 top
R973  -  [R0402_1]  51.98 159.93 90 top
R974  -  [R0402_1]  55.79 159.93 90 top
R975  -  [R0402_1]  58.2 137.45 270 top
R976  -  [R0402_1]  57.18 159.93 90 top
R977  -  [R0402_1]  49.82 137.45 270 top
R978  -  [R0402_1]  163.1 201.96 180 top
R980  -  [R0402_1]  223.43 136.05 0 top
R981  -  [R0402_1]  225.58 136.05 180 top
R982  -  [R0402_1]  217.84 131.1 180 top
R983  -  [R0402_1]  217.84 129.95 180 top
R984  -  [R0402_1]  227.87 131.6 180 top
R985  -  [R0402_1]  221.39 135.29 0 top
R986  -  [R0402_1]  221.52 129.83 0 top
R987  -  [R0402_1]  221.52 133 0 top
R988  -  [R0402_1]  234.35 135.29 180 top
R989  -  [R0402_1]  234.35 134.14 180 top
R990  -  [R0402_1]  189.39 19.97 0 top
R991  -  [R0402_1]  187.1 18.45 0 top
R994  -  [R0402_1]  191.42 14.64 90 top
R995  -  [R0402_1]  190.28 14.64 90 top
R996  -  [R0402_1]  237.27 112.81 270 top
R997  -  [R0402_1]  17.56 87.03 0 top
R998  -  [R0402_1]  17.41 88.17 180 top
R999  -  [R0402_1]  21.37 84.36 0 top
R1000  -  [R0402_1]  9.43 46.26 0 top
R1001  -  [R0402_1]  18.38 204.69 270 top
R1002  -  [R0603_1]  232.82 217.01 0 top
RJ1  -  [RJ3_0402]  62.26 139.1 180 top
RJ2  -  [RJ3_0402]  66.07 138.08 180 top
RJ3  -  [RJ3_0402]  16.03 106.97 270 top
RJ4  -  [RJ3_0402]  14.76 106.97 270 top
RJ5  -  [RJ3_0402]  233.59 15.91 90 top
RJ6  -  [RJ3_0402]  19.72 210.64 180 top
RJ7  -  [RJ3_0402]  195.38 15.4 270 top
RJ8  -  [RJ3_0402]  198.15 21.58 0 top
RJ9  -  [RJ3_0402]  197.39 17.94 0 top
RJ10  -  [RJ3_0402]  198.15 19.21 0 top
RJ11  -  [RJ3_0402]  198.15 20.35 0 top
RJ12  -  [RJ3_0402]  22.79 91.19 270 top
RJ17  -  [RJ3_0402]  196.58 15.4 270 top
RLAN  -  [QFN64_RTL8111DP_1]  51.59 229.27 180 top
RN1  -  [8P4R]  209.65 218.16 0 top
RN2  -  [8P4R]  213.65 218.19 0 top
RN7  -  [8P4R]  177.96 217.96 180 top
RN8  -  [8P4R]  174.02 217.96 180 top
RN9  -  [8P4R-0402]  174.02 214.15 180 top
RN10  -  [8P4R-0402]  177.96 214.15 180 top
RN11  -  [8P4R-0402]  29.78 91.8 90 top
RN12  -  [8P4R-0402]  26.73 91.75 0 top
RN13  -  [8P4R-0402]  41.56 79.92 0 top
RN14  -  [8P4R-0402]  44.1 79.92 0 top
RN15  -  [8P4R-0402]  41.33 64.32 180 top
RN19  -  [8P4R]  12.48 113.19 0 top
RN20  -  [8P4R]  11.08 97.95 180 top
RN21  -  [8P4R]  134.78 213.01 0 top
RN22  -  [8P4R]  128.81 212.88 0 top
RN23  -  [8P4R]  29.75 59.09 90 top
RN24  -  [8P4R]  29.75 51.09 90 top
RN25  -  [8P4R]  29.75 55.15 90 top
RN26  -  [8P4R-0402]  232.82 40.67 90 top
RN27  -  [8P4R-0402]  239.55 221.14 180 top
RN28  -  [8P4R-0402]  231.12 103.92 180 top
RN29  -  [8P4R-0402]  178.98 13.62 180 top
RN30  -  [8P4R-0402]  157.64 13.62 0 top
RN31  -  [8P4R-0402]  173.51 13.62 0 top
RN32  -  [8P4R-0402]  169.96 13.62 180 top
RN33  -  [8P4R-0402]  161.45 13.62 180 top
RN34  -  [8P4R-0402]  164.75 13.62 0 top
RN35  -  [8P4R-0402]  154.21 13.62 180 top
RN38  -  [8P4R]  95.03 213.14 270 top
RN39  -  [8P4R]  111.41 212 0 top
RN40  -  [8P4R]  115.22 212 0 top
RN43  -  [8P4R]  182.02 224.44 0 top
RN44  -  [8P4R]  185.71 224.44 0 top
RN45  -  [8P4R-0402]  27.08 84.36 270 top
RN46  -  [8P4R-0402]  61.37 69.63 270 top
ROM1  -  [SOP8_W150_PT50]  237.01 41.69 180 top
ROM2  -  [SOP8_W210_PT50]  29.62 204.65 90 top
RT1  -  [R0402_1]  212.25 10.45 90 top
RT2  -  [R0402_1]  164.37 183.29 0 top
RT3  -  [R0402_1]  171.23 169.04 270 top
SATA1  -  [SATA3_7P-HI-TOP]  38.89 19.21 270 top
SATA2  -  [SATA3_7P-HI-TOP]  29.36 19.21 270 top
SATA3  -  [SATA3_7P-HI-TOP]  38.87 39.3 270 top
SATA4  -  [SATA3_7P-HI-TOP]  29.37 39.3 270 top
SATA5  -  [SATA3_7P-HI-TOP]  19.84 19.21 270 top
SATA_PWR1  -  [CON6X1_2D5MM-PINREX]  100.93 12.22 270 top
SATA_PWR2  -  [CON6X1_2D5MM-PINREX]  94.01 12.22 270 top
SC1  -  [C0402_1]  93 217.08 180 bottom
SC2  -  [C0402_1]  93 218.6 180 bottom
SC3  -  [C0402_1]  89.31 215.32 180 bottom
SC4  -  [C0402_1]  89.31 216.72 180 bottom
SC5  -  [C0402_1]  85.76 212 180 bottom
SC6  -  [C0402_1]  85.76 213.39 180 bottom
SC7  -  [C0402_1]  89.31 211.61 180 bottom
SC8  -  [C0402_1]  89.31 213.01 180 bottom
SC9  -  [C0402_1]  66.96 95.66 180 bottom
SC10  -  [C0402_1]  92.87 213.01 0 bottom
SC11  -  [C0402_1]  161.96 119.92 0 bottom
SC12  -  [C0402_1]  148.62 131.99 180 bottom
SC14  -  [C0805_1]  148.5 129.7 270 bottom
SC15  -  [C0402_1]  34.81 83.24 180 bottom
SC16  -  [C0402_1]  19.21 109 180 bottom
SC17  -  [C0402_1]  29.62 92.31 180 bottom
SC18  -  [C0402_1]  51.39 100.06 0 bottom
SC19  -  [C0402_1]  47.59 101.25 90 bottom
SC20  -  [C0402_1]  46.51 101.25 90 bottom
SC21  -  [C0603_1]  43.67 101.07 180 bottom
SC22  -  [C0402_1]  50.5 102.01 90 bottom
SC23  -  [C0603_1]  65.44 100.36 90 bottom
SC24  -  [C0603_1]  37.12 107.09 90 bottom
SC25  -  [C0402_1]  40.67 112.05 0 bottom
SC26  -  [C0603_1]  38.77 106.46 90 bottom
SC27  -  [C0402_1]  43.29 93.94 90 bottom
SC28  -  [C0603_1]  66.83 100.36 90 bottom
SC29  -  [C0603_1]  47.2 91.93 0 bottom
SC30  -  [C0402_1]  48.8 94.39 0 bottom
SC31  -  [C0402_1]  48.8 96.74 0 bottom
SC32  -  [C0603_1]  35.34 95.97 0 bottom
SC33  -  [C0603_1]  36.61 87.66 270 bottom
SC34  -  [C0402_1]  42.2 92.49 270 bottom
SC35  -  [C0402_1]  32.93 97.06 180 bottom
SC36  -  [C0402_1]  31.93 100.18 180 bottom
SC37  -  [C0402_1]  69.31 216.57 180 bottom
SC38  -  [C0402_1]  75.22 212.76 0 bottom
SC39  -  [C0402_1]  69.31 214.03 180 bottom
SC40  -  [C0402_1]  74.84 210.73 270 bottom
SC41  -  [C0402_1]  25.31 93.63 0 bottom
SC43  -  [C0402_1]  217.84 132.62 0 bottom
SC44  -  [C0402_1]  93.76 220.76 0 bottom
SC45  -  [C0402_1]  93.76 222.41 0 bottom
SC46  -  [C0402_1]  43.59 228.12 0 bottom
SC48  -  [C0402_1]  133.64 218.22 270 bottom
SC49  -  [C0402_1]  158.02 220.89 180 bottom
SC50  -  [C0402_1]  202.7 25.31 180 bottom
SC51  -  [C0402_1]  202.72 24.16 180 bottom
SC52  -  [C0402_1]  27.06 94.95 180 bottom
SD1  -  [BAT54_132_2]  14.19 10 0 bottom
SD2  -  [SOT23_3L]  96.81 221.39 90 bottom
SFB1  -  [FB0603_1]  91.09 220.76 0 bottom
SFB2  -  [FB0603_1]  91.09 222.28 0 bottom
SHK*  -  [unnamed#3]  46.64 96.81 90 top
SJ1  -  [2X30_XDP_CONN-NMNP]  224.57 127.16 90 bottom
SPI_DEBUG  -  [J6X2_PT1D27MM_SMD_2P]  12.35 7.78 90 top
SPIROM1  -  [SOP8_W210_PT50]  24.42 5.82 90 top
SPIROM2  -  [SOP8_W210_PT50]  38.26 5.82 90 top
SQP1  -  [SOT23_BCE_2]  14.19 14 180 bottom
SR1  -  [R0603_1]  45.75 236.51 180 bottom
SR2  -  [R0402_1]  60.23 221.39 0 bottom
SR3  -  [R0402_1]  60.23 220.25 0 bottom
SR5  -  [R0402_1]  60.23 219.11 0 bottom
SR6  -  [R0402_1]  60.23 218.04 0 bottom
SR7  -  [R0402_1]  83.73 217.84 180 bottom
SR8  -  [R0402_1]  83.73 216.82 180 bottom
SR9  -  [R0402_1]  81.76 215.93 180 bottom
SR10  -  [R0402_1]  81.76 214.92 180 bottom
SR11  -  [R0402_1]  79.36 215.42 90 bottom
SR12  -  [R0402_1]  78.34 215.42 90 bottom
SR13  -  [R0402_1]  85.76 210.98 180 bottom
SR14  -  [R0402_1]  85.76 209.96 180 bottom
SR15  -  [R0603-SHORT_1-NMNP]  18.19 219.74 270 bottom
SR16  -  [R0402_1]  165.74 120.07 0 bottom
SR17  -  [R0402_1]  148.62 126.27 0 bottom
SR18  -  [R0402_1]  148.62 123.98 180 bottom
SR19  -  [R0402_1]  148.62 125.13 0 bottom
SR20  -  [R0402_1]  55.91 107.16 270 bottom
SR21  -  [R0402_1]  49.55 102.01 90 bottom
SR22  -  [R0402_1]  170.15 123.16 270 bottom
SR23  -  [R0402_1]  170.15 121 270 bottom
SR24  -  [R0402_1]  148.62 127.41 180 bottom
SR30  -  [R0402_1]  217.84 131.48 0 bottom
SR32  -  [R0402_1]  231.05 133.51 180 bottom
SR33  -  [R0402_1]  230.16 126.02 90 bottom
SR34  -  [R0402_1]  231.3 126.02 90 bottom
SR36  -  [R0402_1]  231.05 130.84 180 bottom
SR37  -  [R0402_1]  231.05 131.99 180 bottom
SR38  -  [R0402_1]  217.84 133.89 0 bottom
SR40  -  [R0402_1]  217.84 124.75 0 bottom
SR43  -  [R0603_1]  45.88 225.58 90 bottom
SR44  -  [R0603_1]  59.21 233.08 270 bottom
SR45  -  [R0402_1]  88.04 220.76 0 bottom
SR46  -  [R0402_1]  88.04 222.28 0 bottom
SR48  -  [R0402_1]  11.72 14.64 90 bottom
SR49  -  [R0402_1]  11.72 12.48 270 bottom
SR50  -  [R0603_1]  11.72 9.56 90 bottom
SR51  -  [R0402_1]  202.85 27.34 90 bottom
SR52  -  [R0402_1]  204.05 27.34 90 bottom
SR53  -  [R0805_1]  49.44 24.04 90 bottom
SR54  -  [R0402_1]  49.18 21.75 0 bottom
SR55  -  [R0402_1]  200.57 25.31 180 bottom
SR56  -  [R0402_1]  200.57 24.16 180 bottom
SR57  -  [R0402_1]  27.34 88.81 180 bottom
SR58  -  [R0402_1]  27.08 87.28 0 bottom
SR59  -  [R0402_1]  63.91 223.17 90 bottom
STP1  -  [TP30_SMD]  153.83 139.35 180 bottom
STP2  -  [TP30_SMD]  148.37 137.57 180 bottom
STP3  -  [TP30_SMD]  151.16 136.56 180 bottom
STP4  -  [TP30_SMD]  200.82 144.94 180 bottom
STP5  -  [TP30_SMD]  198.41 141.26 180 bottom
STP6  -  [TP30_SMD]  200.82 141.26 180 bottom
STP7  -  [TP30_SMD]  190.28 137.57 180 bottom
STP8  -  [TP30_SMD]  198.41 144.94 180 bottom
STP9  -  [TP30_SMD]  198.41 143.16 180 bottom
STP10  -  [TP30_SMD]  200.82 143.16 180 bottom
STP11  -  [TP30_SMD]  146.59 130.21 180 bottom
STP12  -  [TP30_SMD]  159.67 118.4 180 bottom
STP13  -  [TP30_SMD]  43.57 86.42 180 bottom
STP14  -  [TP30_SMD]  44.69 84.84 180 bottom
STP15  -  [TP30_SMD]  42.7 95.36 180 bottom
STP16  -  [TP30_SMD]  43.72 91.22 180 bottom
STP17  -  [TP30_SMD]  50.45 97.57 180 bottom
STP18  -  [TP30_SMD]  191.93 137.19 180 bottom
STP19  -  [TP30_SMD]  69.5 218.22 180 bottom
SU1  -  [SOT23_6P_2]  96.81 217.2 90 bottom
SU2  -  [SOT23_6P_2]  96.81 213.14 270 bottom
SYS_FAN  -  [FAN4X1]  118.4 178.85 180 top
THER_HD  -  [J3X2_SPDIF]  238.23 33.56 90 top
TP12  -  [TP30_SMD]  152.15 94.09 0 top
TP14  -  [TP30_SMD]  167.57 90.48 0 top
TP15  -  [TP30_SMD]  171.2 95.41 0 top
TP21  -  [TP30_SMD]  71.03 219.11 0 top
TP23  -  [TP30_SMD]  22.26 212.5 0 top
TP_VGA  -  [TP30_SMD]  32.82 90.18 0 top
TPM  -  [J10X2_TPM_4P-ACER]  206.15 5.77 0 top
U1  -  [SOT1059_10P_1]  209.96 221.77 0 top
U2  -  [SOT1059_10P_1]  213.77 221.77 0 top
U3  -  [SOT23_6P_2]  222.54 221.27 0 top
U4  -  [SOT1059_10P_1]  182.4 227.87 0 top
U5  -  [SOT1059_10P_1]  185.71 227.87 0 top
U6  -  [SOT23_6P_2]  190.53 218.6 0 top
U7  -  [SOT23_6P_2]  158.15 221.14 270 top
U8  -  [SOT1059_10P_1]  174.02 221.65 180 top
U9  -  [SOT23_6P_2]  152.81 220.76 0 top
U10  -  [SOT1059_10P_1]  177.96 221.65 0 top
U11  -  [LQFP128_PT04]  58.64 148.69 180 top
U12  -  [SOT23_8P_1]  11.72 106.97 90 top
U13  -  [SOT23_8P_1]  11.59 126.91 0 top
U14  -  [SOT23_6P_2]  12.48 117.51 180 top
U15  -  [SOT23_6P_2]  10.7 93.63 180 top
U16  -  [SOT23_8P_1]  142.53 211.23 0 top
U17  -  [SOT23_6P_2]  134.78 217.2 180 top
U18  -  [SOT23_6P_2]  128.81 217.2 0 top
U19  -  [PSOP8_W150_PT50_PAD-UP7719B_1]  11.72 34.83 270 top
U20  -  [SOT23_6P_2]  25.31 58.83 90 top
U21  -  [QFP128]  213.23 24.16 270 top
U22  -  [SOP8_W150_PT50]  120.05 187.99 270 top
U23  -  [TSSOP28_W170_PT065]  233.08 22.13 0 top
U24  -  [SOT23_6P_2]  164.37 219.62 270 top
U25  -  [SOT23_8P_1]  11.97 136.05 0 top
U26  -  [SOT23_6P_2]  7.78 132.75 180 top
U28  -  [SOT23_6P_2]  99.85 213.14 270 top
U29  -  [PSOP8_W150_PT50_PAD-UP7719B_1]  122.33 206.66 270 top
U30  -  [SOP8_W150_PT50-104X120]  100.87 25.18 180 top
U31  -  [SOP8_W150_PT50]  170.85 21.62 90 top
U32  -  [SOP8_W150_PT50]  98.46 101.25 0 top
U33  -  [DFN10_RT8106A_1]  79.28 63.66 270 top
U34  -  [PSOP8_W150_PT50_PAD-UP6281]  117.51 19.34 90 top
U35  -  [SOT23_5P_1]  167.93 209.96 0 top
U36  -  [SOT23_5P_1]  162.59 209.96 0 top
U39  -  [QFN40_PT04_E2201]  228.51 150.53 90 top
U40  -  [DFN8_PT05_ISL6208_1]  147.1 183.93 0 top
U41  -  [QFN28_SM331L_PT04MM_1]  53.12 33.56 90 top
U42  -  [TSSOP20_W170_PT065]  201.58 214.15 180 top
U43  -  [TSSOP20_W170_PT065]  12.88 24.95 0 top
USB2X4  -  [USBX4_2]  133.1 229.18 180 top
USB3_LAN  -  [RJ45_USB3_32P]  113.92 231.3 180 top
USB3F1  -  [CON10X2_2MM_20P_USB3_1]  18.96 50.58 90 top
VGA  -  [DVI_D-SUB_15F_1]  161.86 237.59 180 top
X1  -  [CRYSTAL]  60.32 127.16 0 top
X2  -  [CRYSTAL]  59.72 213.14 0 top
X3  -  [CRYSTAL]  44.99 214.15 180 top
Y1  -  [ETXTALS-SPAD]  29.24 70.52 270 top

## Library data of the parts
A1 A2 C_INTRUSION FW_DEBUG OBR = J2X1
ATX_12V = ATX_PWR_4P_1
ATX_POWER = ATX_PWR_12P-RUIYE
AUDIO = AUDIO_JACK_13P-KORTAK
BAT1 = BATTERY_1
BIOS_WP CLR_CMOS ME_DISABLE = J3X1
BZ = BUZZER_1
